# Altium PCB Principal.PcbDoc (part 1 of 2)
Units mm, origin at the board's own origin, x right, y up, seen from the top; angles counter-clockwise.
Board outline 45.4 x 70.2 mm, 2 copper layers (Top Layer, Bottom Layer); 50 components, 70 nets, 241 pads, 58 vias.
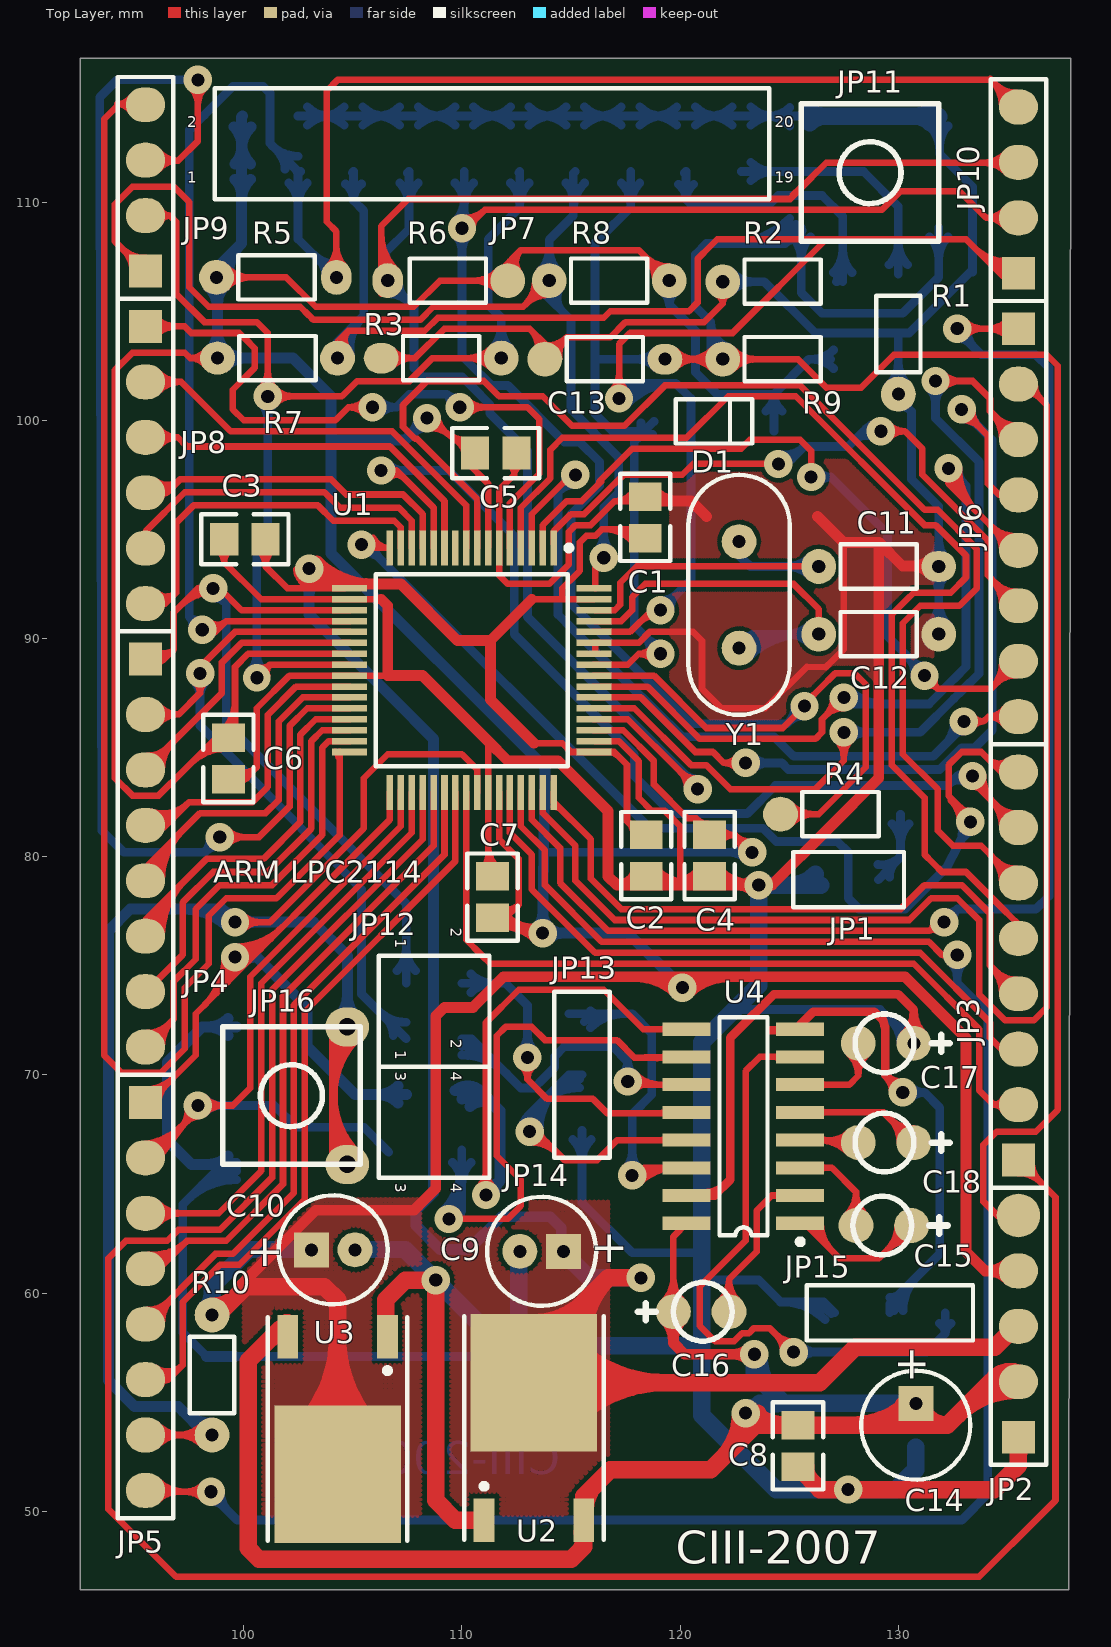
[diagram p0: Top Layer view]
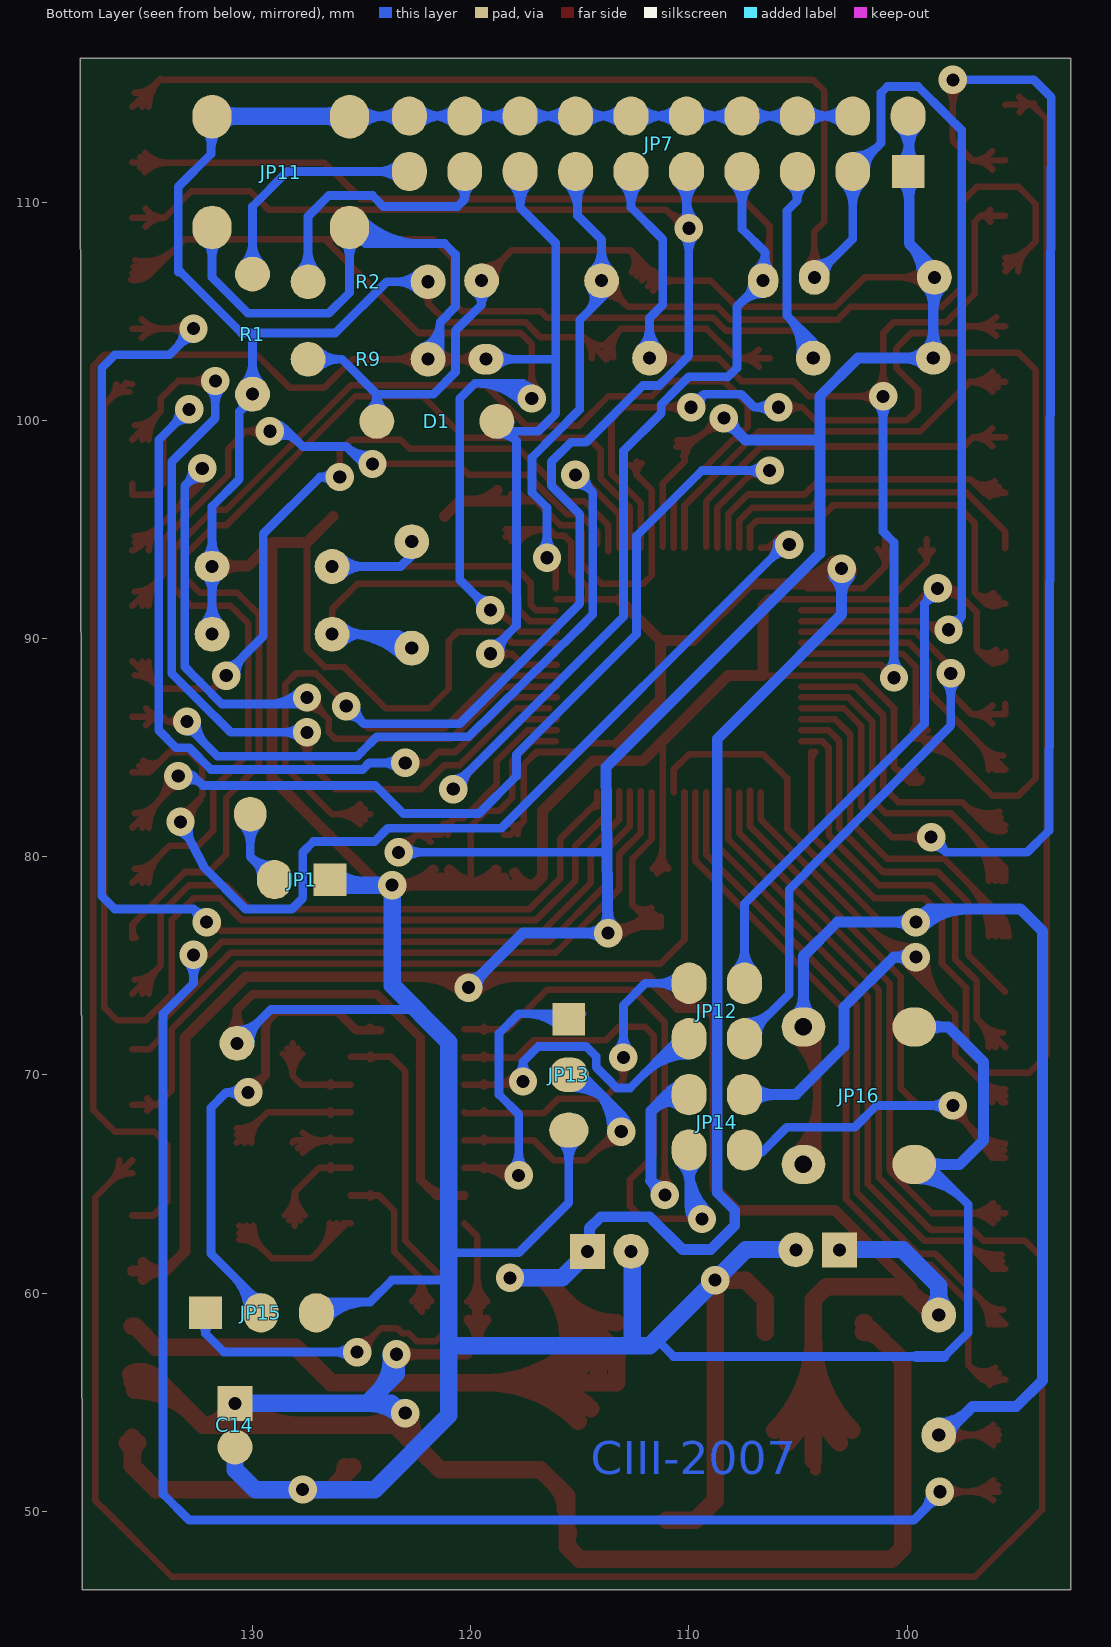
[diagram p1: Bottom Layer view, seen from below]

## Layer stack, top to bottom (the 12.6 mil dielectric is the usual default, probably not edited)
Top Layer: signal copper 0.0356
Dielectric: core 0.32, FR-4, Dk 4.8
Bottom Layer: signal copper 0.0356

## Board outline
92.5,116.4 92.5,46.4 137.8,46.4 137.9,116.6 92.5,116.6

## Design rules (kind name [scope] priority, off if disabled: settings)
Clearance [All] p1: gap=0.2
ComponentClearance [All] p1: gap=0.254 collisioncheckmode=0
PolygonConnect [All] p1: connectstyle=Direct reliefconductorwidth=0.254 reliefentries=4 polygonreliefangle="90 Angle"
RoomDefinition Principal1 [InComponentClass('Principal1')] p1: confinementstyle=ConfineIn formatcopy=TRUE outline 0,0 50.8,0 50.8,25.4 0,25.4
RoutingLayers [All] p1: top layer="Not Used" bottom layer="Not Used"
RoutingVias [All] p1: holewidth=0.711 width=1.27 viastyle="Through Hole" minholewidth=0.711 minwidth=1.27 maxholewidth=0.711 maxwidth=1.27
SolderMaskExpansion [All] p1: expansion=0.102
TestPointUsage [All] p1: valid=0 allowmultiple=FALSE
Testpoint [All] p1: side=15 testpointundercomponent=TRUE minsize=1.016 maxsize=2.54 preferedsize=1.524 minholesize=0 maxholesize=1.016 preferedholesize=0.813 testpointgrid=0.025 style=1023 order=-539222988
Width [All] p1: maxlimit=0.8 minlimit=0.2 preferedwidth=0.2 toplayer_prefwidth=0.3 bottomlayer_prefwidth=0.4 minimp=50.000000 maximp=50.000000 favimp=50.000000
16 further rules are at their usual default settings.

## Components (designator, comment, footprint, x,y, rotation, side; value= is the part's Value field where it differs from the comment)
C1 "Cap" R2012-0805 118.4,95.55 r270 top
C2 "Cap" R2012-0805 118.45,80.05 r90 top
C3 "Cap" R2012-0805 100.05,94.55 r0 top
C4 "Cap" R2012-0805 121.35,80.05 r90 top
C5 "Cap" R2012-0805 111.55,98.5 r180 top
C6 "Cap" R2012-0805 99.3,84.5 r90 top
C7 "Cap" R2012-0805 111.4,78.15 r270 top
C8 "Cap" R2012-0805 125.4,53 r90 top
C9 "Cap" CAPPR2-5x6.8#1 113.652,61.916 r180 top
C10 "Cap" CAPPR2-5x6.8#1 104.098,61.984 r0 top
C11 "Cap" "Res 5mm"#1 126.35,93.3 r0 top
C12 "Cap" "Res 5mm"#2 126.35,90.2 r0 top
C13 "Cap" "Res 5mm"#3 119.3,102.8 r180 top
C14 "Cap Pol1" CAPPR2-5x6.8#2 130.8,53.95 r270 top
C15 "Cap Pol3" CAP_ELECT1#1 130.6,63.1 r180 top
C16 "Cap Pol3" CAP_ELECT1#1 119.7,59.15 r0 top
C17 "Cap Pol3" CAP_ELECT1#2 130.7,71.45 r180 top
C18 "Cap" CAP_ELECT1#1 130.7,66.9 r180 top
D1 "Diode" "Diode 5mm" 118.8,99.95 r0 top
JP1 "JTAG" HDR1X2 126.45,78.95 r0 top
JP2 "Header 5" HDR1X5 135.5,53.4 r90 top
JP3 "Header 8" HDR1X8 135.5,66.1 r90 top
JP4 "Header 8" HDR1X8 95.5,89.06 r270 top
JP5 "Header 8" HDR1X8 95.5,68.74 r270 top
JP6 "Header 8" HDR1X8 135.5,104.2 r270 top
JP7 "JTAG P5" HDR2X10 99.95,111.4 r0 top
JP8 "Header 6" HDR1X6 95.5,104.3 r270 top
JP9 "Header 4" HDR1X4 95.5,106.84 r90 top
JP10 "Header 4" HDR1X4 135.5,106.74 r90 top
JP11 "Header 2" SW1#1 131.85,108.2 r90 top
JP12 "Header 2X2" HDR2X2 107.45,74.2 r270 top
JP13 "Header 3" HDR1X3 115.5,72.55 r270 top
JP14 "Header 2X2" HDR2X2 107.45,69.1 r270 top
JP15 "Header 3" HDR1X3 132.15,59.1 r180 top
JP16 "Header 2" SW1#2 99.035,65.9 r0 top
R1 "Res1" "Res 5mm"#4 130,106.7 r270 top
R2 "Res1" "Res 5mm"#4 127.45,106.35 r180 top
R3 "Res1" "Res 5mm"#5 111.8,102.85 r180 top
R4 "Res1" "Res 5mm"#6 124.6,81.95 r0 top
R5 "Res1" "Res 5mm"#7 98.75,106.55 r0 top
R6 "Res1" "Res 5mm"#8 112.1,106.4 r180 top
R7 "Res1" "Res 5mm"#9 98.8,102.85 r0 top
R8 "Res1" "Res 5mm"#2 119.5,106.4 r180 top
R9 "Res1" "Res 5mm"#10 121.95,102.8 r0 top
R10 "Res1" "Res 5mm"#2 98.55,59 r270 top
U1 "LPC2114/LPC2124" F-QFP10X10-G64/P.5N 110.45,88.55 r270 top
U2 "LD1117S18" KTP02 113.3,52.75 r0 top
U3 "LD1117S33" KTP02 104.3,54.85 r180 top
U4 "MAX232EWE" SO-G16 122.9,67.65 r90 top
Y1 "XTAL 16Mhz" Cristal 122.7,92 r90 top

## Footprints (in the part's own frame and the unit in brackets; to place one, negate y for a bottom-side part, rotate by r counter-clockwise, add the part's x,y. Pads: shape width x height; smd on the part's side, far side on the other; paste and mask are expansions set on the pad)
CAP_ELECT1#1 [mm]
  round 1.6 smd: 1(-0.01,0) 2(2.54,0)
  silkscreen extent -1.65,-1.34 2.68,1.34
CAP_ELECT1#2 [mm]
  round 1.6 hole 0.6: 1(-0.01,0)
  round 1.6 smd: 2(2.54,0)
  silkscreen extent -1.65,-1.34 2.68,1.34
CAPPR2-5x6.8#1 [mm] "Capacitor, Electrolytic, Radial; Body 5 x 6.8 mm (Dia.xH typ); Pin Spacing 2 mm (typ)"
  rect 1.6x1.6 hole 0.6: 1(-1,0)
  round 1.6 hole 0.6: 2(1,0)
  silkscreen extent -2.5,-2.5 2.5,2.5
CAPPR2-5x6.8#2 [mm] "Capacitor, Electrolytic, Radial; Body 5 x 6.8 mm (Dia.xH typ); Pin Spacing 2 mm (typ)"
  rect 1.6x1.6 hole 0.6: 1(-1,0)
  round 1.6 smd far side: 2(1,0)
  silkscreen extent -2.5,-2.5 2.5,2.5
Cristal [mm]
  round 1.6 hole 0.6: 1(-2.44,0) 2(2.44,0)
  silkscreen extent -5.5,-2.32 5.5,2.32
"Diode 5mm" [mm]
  round 1.6 smd far side: 1(0,0) 2(5.5,0)
  silkscreen extent 1,-1.02 4.5,1.02
F-QFP10X10-G64/P.5N [mm]
  rect 1.6x0.3 smd: 1(-5.6,3.75) 2(-5.6,3.25) 3(-5.6,2.75) 4(-5.6,2.25) 5(-5.6,1.75) 6(-5.6,1.25) 7(-5.6,0.75) 8(-5.6,0.25) 9(-5.6,-0.25) 10(-5.6,-0.75) 11(-5.6,-1.25) 12(-5.6,-1.75) 13(-5.6,-2.25) 14(-5.6,-2.75) 15(-5.6,-3.25) 16(-5.6,-3.75) 33(5.6,-3.75) 34(5.6,-3.25) 35(5.6,-2.75) 36(5.6,-2.25) 37(5.6,-1.75) 38(5.6,-1.25) 39(5.6,-0.75) 40(5.6,-0.25) 41(5.6,0.25) 42(5.6,0.75) 43(5.6,1.25) 44(5.6,1.75) 45(5.6,2.25) 46(5.6,2.75) 47(5.6,3.25) 48(5.6,3.75)
  rect 0.3x1.6 smd: 17(-3.75,-5.6) 18(-3.25,-5.6) 19(-2.75,-5.6) 20(-2.25,-5.6) 21(-1.75,-5.6) 22(-1.25,-5.6) 23(-0.75,-5.6) 24(-0.25,-5.6) 25(0.25,-5.6) 26(0.75,-5.6) 27(1.25,-5.6) 28(1.75,-5.6) 29(2.25,-5.6) 30(2.75,-5.6) 31(3.25,-5.6) 32(3.75,-5.6) 49(3.75,5.6) 50(3.25,5.6) 51(2.75,5.6) 52(2.25,5.6) 53(1.75,5.6) 54(1.25,5.6) 55(0.75,5.6) 56(0.25,5.6) 57(-0.25,5.6) 58(-0.75,5.6) 59(-1.25,5.6) 60(-1.75,5.6) 61(-2.25,5.6) 62(-2.75,5.6) 63(-3.25,5.6) 64(-3.75,5.6)
  silkscreen extent -5.72,-4.4 4.4,4.58
HDR1X2 [mm]
  rect 1.5x1.5 smd far side: 1(0,0)
  oval 1.6x1.8 smd far side: 2(2.54,0)
  silkscreen extent -1.27,-1.27 3.81,1.27
HDR1X3 [mm]
  rect 1.5x1.5 smd far side: 1(0,0)
  oval 1.6x1.8 smd far side: 2(2.54,0) 3(5.08,0)
  silkscreen extent -1.27,-1.27 6.35,1.27
HDR1X4 [mm]
  rect 1.5x1.5 smd: 1(0,0)
  oval 1.6x1.8 smd: 2(2.54,0) 3(5.08,0) 4(7.62,0)
  silkscreen extent -1.27,-1.27 8.89,1.27
HDR1X5 [mm]
  rect 1.5x1.5 smd: 1(0,0)
  oval 1.6x1.8 smd: 2(2.54,0) 3(5.08,0) 4(7.62,0)
  round 2 smd: 5(10.16,0)
  silkscreen extent -1.27,-1.27 11.43,1.27
HDR1X6 [mm]
  rect 1.5x1.5 smd: 1(0,0)
  oval 1.6x1.8 smd: 2(2.54,0) 3(5.08,0) 4(7.62,0) 5(10.16,0) 6(12.7,0)
  silkscreen extent -1.27,-1.27 13.97,1.27
HDR1X8 [mm]
  rect 1.5x1.5 smd: 1(0,0)
  oval 1.6x1.8 smd: 2(2.54,0) 3(5.08,0) 4(7.62,0) 5(10.16,0) 6(12.7,0) 7(15.24,0) 8(17.78,0)
  silkscreen extent -1.27,-1.27 19.05,1.27
HDR2X2 [mm]
  oval 1.9x1.6 smd far side: 1(0,0) 2(0,2.54) 3(2.54,0) 4(2.54,2.54)
  silkscreen extent -1.27,-1.27 3.81,3.81
HDR2X10 [mm]
  rect 1.5x1.5 smd far side: 1(0,0)
  oval 1.6x1.8 smd far side: 2(0,2.54) 3(2.54,0) 4(2.54,2.54) 5(5.08,0) 6(5.08,2.54) 7(7.62,0) 8(7.62,2.54) 9(10.16,0) 10(10.16,2.54) 11(12.7,0) 12(12.7,2.54) 13(15.24,0) 14(15.24,2.54) 15(17.78,0) 16(17.78,2.54) 17(20.32,0) 18(20.32,2.54) 19(22.86,0) 20(22.86,2.54)
  silkscreen extent -1.27,-1.27 24.13,3.81
KTP02 [mm] "PowerFLEX (D-PAK/TO-252-AA); 3 Leads (1 Cropped); Body 9.7 (inc. leads) x 6.2 mm (LxW max)"
  rect 0.95x2 smd: 1(-2.285,-3.15) 3(2.285,-3.15)
  rect 5.8x6.3 smd: 4(0,3.15)
  silkscreen extent -3.2,-4.05 3.2,6.2
R2012-0805 [mm]
  rect 1.3x1.5 smd: 1(-0.95,0) 2(0.95,0)
  silkscreen extent -2,-1.15 2,1.15
"Res 5mm"#1 [mm]
  round 1.6 hole 0.6: 1(0,0)
  oval 1.6x1.4 hole 0.6: 2(5.5,0)
  silkscreen extent 1,-1.02 4.5,1.02
"Res 5mm"#2 [mm]
  round 1.6 hole 0.6: 1(0,0) 2(5.5,0)
  silkscreen extent 1,-1.02 4.5,1.02
"Res 5mm"#3 [mm]
  oval 1.6x1.4 hole 0.6: 1(0,0)
  round 1.6 smd: 2(5.5,0)
  silkscreen extent 1,-1.02 4.5,1.02
"Res 5mm"#4 [mm]
  round 1.6 smd far side: 1(0,0)
  round 1.6 hole 0.6: 2(5.5,0)
  silkscreen extent 1,-1.02 4.5,1.02
"Res 5mm"#5 [mm]
  round 1.6 hole 0.6: 1(0,0)
  oval 1.6x1.4 smd: 2(5.5,0)
  silkscreen extent 1,-1.02 4.5,1.02
"Res 5mm"#6 [mm]
  round 1.6 smd: 1(0,0)
  oval 1.5x1.6 smd far side: 2(5.5,0)
  silkscreen extent 1,-1.02 4.5,1.02
"Res 5mm"#7 [mm]
  round 1.6 hole 0.6: 1(0,0)
  oval 1.4x1.6 hole 0.6: 2(5.5,0)
  silkscreen extent 1,-1.02 4.5,1.02
"Res 5mm"#8 [mm]
  round 1.6 smd: 1(0,0)
  oval 1.4x1.6 hole 0.6: 2(5.5,0)
  silkscreen extent 1,-1.02 4.5,1.02
"Res 5mm"#9 [mm]
  oval 1.6x1.5 hole 0.6: 1(0,0)
  round 1.6 hole 0.6: 2(5.5,0)
  silkscreen extent 1,-1.02 4.5,1.02
"Res 5mm"#10 [mm]
  round 1.6 hole 0.6: 1(0,0)
  round 1.6 smd far side: 2(5.5,0)
  silkscreen extent 1,-1.02 4.5,1.02
SO-G16 [mm]
  rect 0.6x2.2 smd: 1(-4.445,-2.6) 2(-3.175,-2.6) 3(-1.905,-2.6) 4(-0.635,-2.6) 5(0.635,-2.6) 6(1.905,-2.6) 7(3.175,-2.6) 8(4.445,-2.6) 9(4.445,2.6) 10(3.175,2.6) 11(1.905,2.6) 12(0.635,2.6) 13(-0.635,2.6) 14(-1.905,2.6) 15(-3.175,2.6) 16(-4.445,2.6)
  silkscreen extent -5.42,-2.72 5,1.1
SW1#1 [mm]
  oval 2x1.8 smd far side: 1(0.635,6.3) 1(0.635,0) 2(5.715,6.3) 2(5.715,0)
  silkscreen extent 0,0 6.3,6.3
SW1#2 [mm]
  oval 2x1.8 smd far side: 1(0.635,0) 1(0.635,6.3)
  oval 2x1.8 hole 0.8: 2(5.715,0) 2(5.715,6.3)
  silkscreen extent 0,0 6.3,6.3

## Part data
C1 C2 C3 C4 C5 C6 C7 C8 C9 C10 C11 C12 C13: "Capacitor"
C14: "Polarized Capacitor (Radial)"
C15 C16 C17: "Polarized Capacitor (Surface Mount)"
C18: library part "Cap Pol3", "Polarized Capacitor (Surface Mount)"
D1: "Default Diode"
JP1 JP2: library part "Header 2", "Header, 2-Pin"
JP3 JP4 JP5 JP6: "Header, 8-Pin"
JP7: library part "Header 10X2", "Header, 10-Pin, Dual row"
JP8: "Header, 6-Pin"
JP9: library part "Header 8", "Header, 8-Pin"
JP10: "Header, 4-Pin"
JP11 JP16: "Header, 2-Pin"
JP12 JP14: "Header, 2-Pin, Dual row"
JP13 JP15: "Header, 3-Pin"
R1 R2 R3 R4 R5 R6 R7 R8 R9 R10: "Resistor"
U2 U3: library part LF27ACDT, "Very Low Drop Voltage Regulator with Inhibit"
U4: "+5V Powered RS-232 Driver/Receiver"
Y1: library part XTAL, "Crystal Oscillator"

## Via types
v1: diameter 1.3, hole 0.6, Top Layer to Bottom Layer, 57 vias
v2: diameter 1.27, hole 0.6, Top Layer to Bottom Layer, 1 vias

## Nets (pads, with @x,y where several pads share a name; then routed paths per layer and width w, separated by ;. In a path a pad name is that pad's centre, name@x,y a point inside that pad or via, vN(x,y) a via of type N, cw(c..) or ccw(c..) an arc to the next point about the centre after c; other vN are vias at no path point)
GND: C1.1 C2.1 C3.1 C4.1 C5.1 C6.1 C7.1 C8.1 C9.2 C10.2 C11.2 C12.2 C13.2 C14.2 C17.1 JP1.1 JP2.1 JP7.4 JP7.6 JP7.8 JP7.10 JP7.12 JP7.14 JP7.16 JP7.18 JP7.20 JP11.2 JP13.3 JP15.3 JP16.1 R1.2 R2.2 R3.2 U1.6 U1.18 U1.25 U1.42 U1.50 U1.58 U1.59 U2.1 U3.1 U4.15 | length 502.5
  Top Layer w0.3: C3.1@98.817,94.038 cw(c98.448,93.5) 99.1,93.5 ; C3.1@99.1,94.55 99.1,93.5 ; C6.1@99.3,83.55 100.1,83.6 100.6,84.1 ; C6.1@99.349,83.464 ccw(c99.644,83.962) 100.053,83.553 ; C3.1@99.383,94.038 ccw(c99.752,93.5) 99.1,93.5 ; C6.1@99.502,83.722 ccw(c99.847,84.306) 100.326,83.826 ; C6.1@99.654,83.98 ccw(c100.05,84.65) 100.6,84.1 ; C6.1@99.846,83.777 ccw(c100.13,83.921) 100.15,83.603 ccw(c100.169,83.293) C6.1@99.874,83.391 ; 106.3,91.8 U1.18@104.85,91.8 101.9,91.8 100.8,91.8 99.1,93.5 ; R3.2@106.3,102.85 107.85,102.85 109.2,104.2 113.1,104.2 113.8,103.5 C13.2@113.8,102.8 114.8,103.8 ; 106.6,88.3 105.9,88.3 U1.25@104.85,88.3 102.1,88.3 100.6,86.8 100.6,84.1 ; R3.2@106.789,102.461 cw(c107.728,101.522) 107.728,102.85 cw(c107.728,104.178) R3.2@106.789,103.239 ; C7.1@110.946,79.454 ccw(c110.334,80.066) 111.2,80.066 ; C7.1@111.2,79.4 111.2,85.3 ; 111.2,79.824 ccw(c112.024,79.824) C7.1@111.441,79.241 ; 111.2,80.549 ccw(c112.749,80.549) C7.1@111.654,79.454 ; C5.1@112.163,98.03 cw(c111.675,97.495) 112.4,97.495 cw(c112.883,97.495) C5.1@112.695,97.94 ; C5.1@112.4,98.1 112.4,97.5 111.7,96.8 U1.6@111.7,94.15 111.7,92.9 112.1,92.5 114,92.5 114.9,93.4 114.9,94.893 115.207,95.2 115.9,95.2 116.5,95.8 117,96.3 ; 113.117,104.183 cw(c112.172,103.239) C13.2@113.462,102.891 ; 113.484,103.816 cw(c112.75,103.083) C13.2@113.752,102.813 ; C13.2@113.85,103.448 ccw(c113.942,104.658) 114.8,103.8 ; C13.2@114.448,102.85 cw(c115.658,102.942) 114.8,103.8 ; U1.59@116.05,89.8 118.1,89.8 118.6,90.3 120.6,90.3 121,89.9 121,87.7 121.9,86.8 123.9,86.8 125.8,88.7 126.682,88.69 126.972,88.979 126.99,88.99 127.5,89.5 127.5,94.4 ; U1.50@116.1,85.3 117.186,85.3 118.1,84.386 118.1,82.7 118.7,82.1 119.3,82.1 120,81.4 120,78.7 ; U1.58@116.1,89.3 U1.59@116.1,89.8 ; 117.557,96.3 ccw(c117.557,96.99) C1.1@118.133,96.61 ; 117.576,96.3 cw(c117.576,95.776) C1.1@117.946,96.146 ; C1.1@117.883,96.775 cw(c117,97.357) 117,96.3 ; C1.1@118.2,96.3 117,96.3 ; R2.2@121.686,105.756 cw(c121.506,105.35) 121.95,105.35 ; R2.2@121.95,106.35 121.95,105.35 ; R2.2@122.214,105.756 ccw(c122.394,105.35) 121.95,105.35 ; 114.8,103.8 116.8,103.8 117.5,104.5 121.1,104.5 121.95,105.35
  Top Layer w0.4: U4.15@120.3,64.475 121.575,64.475 122.3,65.2 122.3,71.7 122.596,71.996 124.3,73.7 130,73.7 130.71,72.99 C17.1@130.71,71.45 ; U4.15@121.1,64.575 ccw(c121.1,65.963) 122.082,64.982 ; C17.1@130.286,71.874 ccw(c129.261,72.898) 130.71,72.898 ccw(c132.159,72.898) C17.1@131.134,71.874
  Top Layer w0.5: 106.3,91.8 106.6,91.5 106.6,88.3 108.2,88.3 111.2,85.3 112.1,84.4 114.4,84.4 116.7,82.1 116.7,79.1 117.1,78.7 ; C2.1@117.987,79.268 cw(c117.1,79.677) 117.1,78.7 ; C1.1@118.2,96.3 120.5,96.3 121.2,95.6 ; C2.1@118.479,79.029 ccw(c119.274,79.824) 119.274,78.7 ; C1.1@118.783,96.783 ccw(c119.949,97.949) 119.949,96.3 ; C2.1@118.833,79.383 ccw(c120.481,81.031) 120.481,78.7 ; 119.319,78.7 ccw(c119.319,81.031) C4.1@120.967,79.383 ; 120.526,78.7 ccw(c120.526,79.824) C4.1@121.321,79.029 ; C4.1@121.379,79.029 ccw(c122.174,79.824) 122.174,78.7 ; C4.1@121.733,79.383 ccw(c123.381,81.031) v1@123.381,78.7 ; v1@123.328,78.428 ccw(c122.671,77.771) 122.671,78.7 ccw(c122.671,79.629) v1@123.328,78.972 ; 126.3,95.6 127.5,94.4 129.114,94.4 ; 126.45,80.95 126.8,81.3 ; 130.63,93.314 cw(c130.63,92.18) C11.2@131.432,92.982 ; 130.698,93.314 ccw(c130.698,94.352) C11.2@131.432,93.618 ; C11.2@131.5,93.314 130.2,93.314 129.114,94.4 ; 117.1,78.7 124.2,78.7 126.8,81.3 ; 126.8,81.3 129.1,83.6 129.1,94.386 129.114,94.4
  Top Layer w0.8: U3.1@106.5,58.2 106.5,59.7 107.4,60.6 v1(108.8,60.6) 108.8,50.5 109.7,49.6 U2.1@111.015,49.6 ; C8.1@125.4,52.05 126.4,51 134.4,51 135.5,52.1 JP2.1@135.5,53.4 ; C8.1@125.75,52.044 ccw(c126.6,52.023) C8.1@125.984,51.436 ; JP2.1@135.253,53.153 cw(c134.655,52.555) 135.5,52.555 cw(c136.345,52.555) JP2.1@135.747,53.153
  Bottom Layer w0.4: 97.391,64.256 cw(c99.67,61.977) JP16.1@99.67,65.2 ; 98.074,64.939 cw(c99.67,63.343) JP16.1@99.67,65.6 ; 98.3,57.1 97.2,58.2 97.2,64.065 JP16.1@99.035,65.9 ; JP16.1@98.757,65.622 cw(c99.67,64.708) JP16.1@99.67,66 ; 99.6,57.1 110.7,57.1 111.5,57.9 ; JP7.4@102.49,113.94 129.5,113.94 ; JP7.4@102.914,113.516 cw(c103.939,112.491) 103.939,113.94 cw(c103.939,115.389) JP7.4@102.914,114.364 ; JP7.6@104.606,113.516 ccw(c103.581,112.491) 103.581,113.94 ccw(c103.581,115.389) JP7.6@104.606,114.364 ; JP7.6@105.454,113.516 cw(c106.479,112.491) 106.479,113.94 cw(c106.479,115.389) JP7.6@105.454,114.364 ; JP7.8@107.146,113.516 ccw(c106.121,112.491) 106.121,113.94 ccw(c106.121,115.389) JP7.8@107.146,114.364 ; JP7.8@107.994,113.516 cw(c109.019,112.491) 109.019,113.94 cw(c109.019,115.389) JP7.8@107.994,114.364 ; JP7.10@109.686,113.516 ccw(c108.661,112.491) 108.661,113.94 ccw(c108.661,115.389) JP7.10@109.686,114.364 ; JP7.10@110.534,113.516 cw(c111.559,112.491) 111.559,113.94 cw(c111.559,115.389) JP7.10@110.534,114.364 ; JP7.12@112.226,113.516 ccw(c111.201,112.491) 111.201,113.94 ccw(c111.201,115.389) JP7.12@112.226,114.364 ; JP7.12@113.074,113.516 cw(c114.099,112.491) 114.099,113.94 cw(c114.099,115.389) JP7.12@113.074,114.364 ; JP7.14@114.766,113.516 ccw(c113.741,112.491) 113.741,113.94 ccw(c113.741,115.389) JP7.14@114.766,114.364 ; JP13.3@115.076,67.046 cw(c114.051,66.021) 115.5,66.021 cw(c116.949,66.021) JP13.3@115.924,67.046 ; JP13.3@115.5,67.47 115.5,64.149 117.8,61.849 121,61.849 ; JP7.14@115.614,113.516 cw(c116.639,112.491) 116.639,113.94 cw(c116.639,115.389) JP7.14@115.614,114.364 ; JP7.16@117.306,113.516 ccw(c116.281,112.491) 116.281,113.94 ccw(c116.281,115.389) JP7.16@117.306,114.364 ; JP7.16@118.154,113.516 cw(c119.179,112.491) 119.179,113.94 cw(c119.179,115.389) JP7.16@118.154,114.364 ; JP7.18@119.846,113.516 ccw(c118.821,112.491) 118.821,113.94 ccw(c118.821,115.389) JP7.18@119.846,114.364 ; JP7.18@120.694,113.516 cw(c121.719,112.491) 121.719,113.94 cw(c121.719,115.389) JP7.18@120.694,114.364 ; 121,60.6 123.6,60.6 124.6,59.6 126.57,59.6 JP15.3@127.07,59.1 ; R2.2@121.95,106.35 123.85,106.35 126.2,104 130.5,104 133.3,106.8 133.4,106.8 133.4,110.7 131.9,112.2 JP11.2@131.9,113.915 ; R2.2@122.374,105.926 cw(c123.399,104.901) 123.399,106.35 cw(c123.399,107.799) R2.2@122.374,106.774 ; JP7.20@122.386,113.516 ccw(c121.361,112.491) 121.361,113.94 ccw(c121.361,115.389) JP7.20@122.386,114.364 ; 122.6,73.1 122.7,73 129.16,73 C17.1@130.71,71.45 ; JP7.20@123.234,113.516 cw(c124.259,112.491) 124.259,113.94 cw(c124.259,115.389) JP7.20@123.234,114.364 ; 123.941,113.94 cw(c123.941,112.406) JP11.2@125.026,113.491 ; 124.062,113.94 ccw(c124.062,115.303) JP11.2@125.026,114.339 ; 124.656,59.6 cw(c124.656,56.786) JP15.3@126.646,58.776 ; 125.621,59.6 cw(c125.621,57.751) JP15.3@126.929,59.059 ; JP11.2@126.074,113.491 cw(c127.159,112.406) 127.159,113.94 ; JP11.2@126.074,114.339 ccw(c127.038,115.303) 127.038,113.94 ; R1.2@129.576,101.624 ccw(c128.551,102.649) 130,102.649 ccw(c131.449,102.649) R1.2@130.424,101.624 ; R1.2@129.9,101.2 R1.2@129.939,101.151 ; R1.2@130,101.075 R1.2@130.3,100.7 ; 130,104 130,101 130.6,100.4 130.6,97.3 131.85,96.05 C12.2@131.85,89.95 ; C17.1@130.11,71.45 ccw(c128.661,71.45) 129.686,72.474 ccw(c130.71,73.498) C17.1@130.71,72.05 ; R1.2@130.122,100.613 cw(c130.207,100.207) 130.5,100.5 cw(c130.681,100.681) R1.2@130.477,100.836 ; C12.2@131.426,90.624 ccw(c130.401,91.649) 131.85,91.649 ccw(c133.299,91.649) C12.2@132.274,90.624 ; JP11.2@131.426,113.491 cw(c130.281,112.346) 131.9,112.346 ; C11.2@131.496,92.946 cw(c130.643,92.093) 131.85,92.093 cw(c133.057,92.093) C11.2@132.204,92.946 ; C11.2@131.496,93.654 ccw(c130.643,94.507) 131.85,94.507 ccw(c133.057,94.507) C11.2@132.204,93.654 ; 131.9,112.587 cw(c133.178,112.587) JP11.2@132.274,113.491
  Bottom Layer w0.5: 98.3,57.1 99.6,57.1 ; JP16.1@99.281,65.511 ccw(c98.342,64.572) 98.342,65.9 ccw(c98.342,67.228) JP16.1@99.281,66.289 ; JP16.1@99.281,71.811 ccw(c98.342,70.872) 98.342,72.2 ccw(c98.342,73.528) JP16.1@99.281,72.589 ; JP16.1@99.67,65.9 97.6,65.9 96.5,67 96.5,70.6 98.1,72.2 JP16.1@99.67,72.2
  Bottom Layer w0.8: C10.2@105.2,62 107.4,62 111.8,57.6 120.9,57.6 121,57.5 ; C9.2@112.391,61.791 cw(c111.886,61.286) C9.2@112.6,61.286 ; 112.5,57.6 112.55,57.65 ; 112.6,57.6 C9.2@112.6,61.9 ; 125.002,78.7 ccw(c125.002,80.398) JP1.1@126.202,79.197 ; JP11.2@125.933,113.632 cw(c126.676,112.889) 126.676,113.94 ; JP11.2@125.933,114.198 ccw(c126.555,114.82) 126.555,113.94 ; JP11.2@126,113.94 131.825,113.94 JP11.2@131.85,113.915 ; JP1.1@126.45,78.7 v1(123.6,78.7) 123.6,74.1 121,71.5 121,54.4 124.4,51 129.882,51 130.527,51.645 130.8,51.918 C14.2@130.8,52.95 ; 130.724,113.94 cw(c130.724,112.889) JP11.2@131.467,113.632 ; 130.845,113.94 ccw(c130.845,114.82) JP11.2@131.467,114.198
  other v1: 127.7,51
NetC1_2: C1.2 C2.2 C3.2 C9.1 JP2.3 U1.17 U1.49 U1.63 U2.4 | length 169.5
  Top Layer w0.3: C3.2@100.659,94.084 cw(c99.928,93.3) 101,93.3 ; C3.2@101,94.55 101,93.3 ; C3.2@101.341,94.084 ccw(c102.072,93.3) 101,93.3 ; v1@102.413,93.167 ccw(c103.33,93.219) 103.33,92.3 ; v1@102.712,93.184 ccw(c103.648,93.237) 103.648,92.3 ; v1@103.012,93.201 ccw(c103.965,93.255) 103.965,92.3 ; v1@103.312,93.218 ccw(c104.283,93.273) U1.17@104.283,92.3 ; v1@103.611,93.235 ccw(c104.6,93.291) 104.6,92.3 102,92.3 101,93.3 ; 113.2,91.8 U1.63@116.05,91.8 ; 113.3,85.2 114.6,85.2 115,84.8 116.979,84.8 117.564,84.215 117.564,81.636 118.2,81 C2.2@118.45,81 ; 114.6,91.8 114.6,92.3 115.202,92.897 115.4,93.1 ; 115.2,92.9 115.4,93.1 ; 116.6,95 cw(c116.6,93.445) C1.2@117.886,94.319 ; U1.49@116.7,84.8 cw(c116.7,84.127) 117.176,84.603 ; 117.167,95 cw(c117.167,93.83) C1.2@118.135,94.488 ; C1.2@117.733,95 cw(c117.733,94.215) C1.2@118.383,94.656 ; C2.2@117.85,81.02 ccw(c117.127,81.049) 117.639,81.561 ccw(c117.972,81.894) C2.2@118.155,81.46 ; C1.2@118.4,95 116.407,95 116.107,94.7 115.7,94.7 115.5,94.5 115.4,94.4 115.4,93.1
  Top Layer w0.5: v1@102.655,92.855 ccw(c103.512,93.712) 103.512,92.5 ; v1(103,93.2) 103.7,92.5 ; v1@103.008,93.208 ccw(c104.719,94.919) 104.719,92.5 ; v1@103.086,92.695 cw(c103.204,92.004) 103.7,92.5 ; v1@103.362,93.562 ccw(c105.926,96.126) 105.926,92.5 ; v1@103.505,93.114 ccw(c104.196,92.996) 103.7,92.5 ; 113.2,91.8 111.3,89.9 ; 113.3,85.2 111.3,87.2 111.3,89.9 ; 103.7,92.5 107.2,92.5 109.8,89.9 111.3,89.9
  Top Layer w0.8: U2.4@113.3,58.65 ccw(c113.3,61.909) 115.605,59.605 ; U2.4@114.165,56.399 cw(c116.493,57.067) U2.4@114.78,58.78 ; U2.4@114.502,54.698 cw(c117.404,51.796) 117.404,55.9 cw(c117.404,60.004) U2.4@114.502,57.102 ; U2.4@114.934,56.619 cw(c117.984,57.496) 115.74,59.74 ; U2.4@115.068,54.132 cw(c119.336,49.864) 119.336,55.9 cw(c119.336,61.936) U2.4@115.068,57.668 ; U2.4@115.703,56.84 cw(c119.475,57.924) 116.7,60.7 ; v1(118.2,60.7) 116.7,60.7 ; JP2.3@135.5,58.48 135.38,58.48 134.423,57.523 128.023,57.523 126.4,55.9 U2.4@113.3,55.9 113.3,57.3 116.7,60.7
  Bottom Layer w0.5: v1@102.638,92.838 cw(c101.764,91.964) 103,91.964 cw(c104.236,91.964) v1@103.362,92.838 ; v1(103,93.2) 103,91.1 106.837,87.263 108.7,85.4 108.7,64.6 107.9,63.8 107.9,63.1 109,62 110.3,62 111.8,63.5 114.032,63.5 114.55,62.982 C9.1@114.55,61.95
  Bottom Layer w0.8: C9.1@114.55,61.95 115.8,60.7 v1(118.2,60.7)
NetC4_2: C4.2 C5.2 C6.2 C7.2 C10.1 D1.2 JP2.4 JP7.1 JP7.2 R5.1 R6.1 R7.1 R8.1 R9.2 R10.1 U1.7 U1.23 U1.43 U1.51 U3.4 | length 344
  Top Layer w0.3: 97.578,84.278 cw(c99.2,82.657) C6.2@99.2,84.95 ; 98.09,84.79 cw(c99.2,83.681) C6.2@99.2,85.25 ; R7.1@98.27,102.49 ccw(c97.55,101.95) 97.55,102.85 ; R7.1@98.27,103.21 cw(c97.55,103.75) 97.55,102.85 ; R7.1@98.6,102.85 97.55,102.85 ; R5.1@98.75,106.55 101.95,106.55 103.3,105.2 107.793,105.2 108.993,106.4 111.8,106.4 111.8,106.9 112.7,107.8 ; R5.1@98.997,106.303 cw(c99.595,105.705) 99.595,106.55 cw(c99.595,107.395) R5.1@98.997,106.797 ; C6.2@99.046,85.804 ccw(c97.71,87.14) 99.6,87.14 ; R5.1@99.21,106.09 cw(c100.319,104.981) 100.319,106.55 cw(c100.319,108.119) R5.1@99.21,107.01 ; C6.2@99.259,85.591 ccw(c98.434,86.416) 99.6,86.416 ; 99.6,86.174 ccw(c100.124,86.174) C6.2@99.754,85.804 ; U1.23@104.85,89.3 100.2,89.3 99.6,88.7 99.6,85.4 98.7,85.4 97.3,84 96.1,82.8 94.9,82.8 94.1,83.6 94.1,102.3 94.9,103.1 97.3,103.1 97.55,102.85 ; v1(108.4,100.1) 110.1,98.8 C5.2@110.25,98.35 ; v1@108.464,99.619 cw(c108.619,98.459) 109.33,99.389 cw(c110.041,100.319) v1@108.881,100.164 ; 109.275,99.431 ccw(c110.309,100.782) C5.2@110.534,99.096 ; 109.831,99.006 cw(c109.398,98.44) C5.2@110.104,98.534 ; 109.851,98.991 ccw(c110.444,99.767) C5.2@110.574,98.798 ; C5.2@110.2,98.65 110.2,98.1 111.2,97.1 U1.7@111.2,94.2 ; C7.2@111.417,77.144 ccw(c112.067,77.585) C7.2@112.067,76.8 ; C7.2@111.587,77.38 ccw(c111.859,77.944) 112.301,77.501 ; R6.1@111.64,105.94 ccw(c110.531,104.831) 110.531,106.4 ccw(c110.531,107.969) R6.1@111.64,106.86 ; C7.2@111.665,77.312 ccw(c112.633,77.97) 112.633,76.8 ; U1.43@111.7,82.95 111.7,80.8 112.6,79.9 112.6,77.8 ; C7.2@111.717,77.65 ccw(c112.053,78.347) 112.6,77.8 ; C7.2@111.805,76.8 cw(c111.805,74.605) v1@113.357,76.157 ; R6.1@111.853,106.153 ccw(c111.255,105.555) 111.255,106.4 ccw(c111.255,107.245) R6.1@111.853,106.647 ; C7.2@111.914,77.481 ccw(c113.2,78.355) v1@113.2,76.8 ; R6.1@112.14,106.43 cw(c112.683,106.83) 112.206,107.306 ; R6.1@112.382,106.608 cw(c112.968,107.039) 112.453,107.553 ; 112.529,76.8 cw(c112.529,75.329) v1@113.569,76.369 ; R6.1@112.623,106.785 cw(c113.252,107.248) 112.7,107.8 ; v1(113.7,76.5) v1@113.2,76.8 ; U1.51@116.05,85.8 117.393,85.8 118.8,84.393 118.8,83.307 120.339,81.768 120.732,81.768 ; R8.1@118.85,106.4 ccw(c117.281,106.4) 118.39,107.51 ccw(c119.5,108.619) R8.1@119.5,107.05 ; R8.1@119.15,106.4 ccw(c118.305,106.4) 118.903,106.997 ccw(c119.5,107.595) R8.1@119.5,106.75 ; R8.1@119.5,106.4 118.1,107.8 112.7,107.8 ; 120.823,81.677 ccw(c121.25,82.104) C4.2@121.25,81.5 ; C4.2@121.05,81 ccw(c119.964,81) 120.732,81.768 ; C4.2@121.2,81.3 120.732,81.768 ; C4.2@121.35,81 122.5,81 ; C4.2@121.4,81.1 121.425,81.075 C4.2@121.5,81 ; C4.2@121.838,80.685 cw(c122.5,80.148) 122.5,81 ; C4.2@121.838,81.315 ccw(c122.5,81.852) 122.5,81 ; v1@122.815,80.212 ccw(c121.739,80.238) 122.5,81 ccw(c123.262,81.761) v1@123.288,80.685 ; v1(123.3,80.2) 122.5,81 ; 112.6,77.8 112.05,77.25 111.3,77.25 111.3,76.8 v1@113.2,76.8
  Top Layer w0.5: 99.8,60.3 103.3,63.8 107.8,63.8 108.8,64.8 108.8,72.7 109.2,73.1 110.5,73.1 111.9,74.5 130.3,74.5 133.1,71.7 133.1,61.9 133.98,61.02 JP2.4@135.5,61.02 ; U3.4@104.204,51.9 U3.4@104.204,52.35 ; 117.963,74.5 cw(c117.963,71.863) v1@119.828,73.728 ; 119.171,74.5 cw(c119.171,73.071) v1@120.181,74.081 ; v1@120.019,74.081 cw(c121.029,73.071) 121.029,74.5 ; v1@120.372,73.728 cw(c122.237,71.863) 122.237,74.5 ; JP2.4@135.011,60.631 ccw(c134.072,59.692) 134.072,61.02 ccw(c134.072,62.348) JP2.4@135.011,61.409
  Top Layer w0.8: R10.1@98.55,59 98.8,59 100.1,60.3 103.7,60.3 104.3,59.7 U3.4@104.3,52.35 ; R10.1@98.55,59.4 ccw(c98.55,60.969) 99.66,59.86 ; U3.4@102.532,53.718 ccw(c98.264,57.986) 104.3,57.986 ccw(c110.336,57.986) U3.4@106.068,53.718 ; U3.4@103.098,53.152 ccw(c100.196,56.054) 104.3,56.054 ccw(c108.404,56.054) U3.4@105.502,53.152
  Bottom Layer w0.4: 113.7,80.2 v1(123.3,80.2) ; R8.1@119.175,105.896 cw(c118.792,105.3) 119.5,105.3 ; R8.1@119.5,106.4 119.5,105.3 ; R8.1@119.825,105.896 ccw(c120.208,105.3) 119.5,105.3 ; v1@122.992,79.892 ccw(c122.25,79.15) 122.25,80.2 ccw(c122.25,81.25) v1@122.992,80.508 ; D1.2@123.925,100.418 ccw(c123.298,101.2) 124.3,101.2 ; D1.2@124.3,99.5 124.3,101.2 ; D1.2@124.675,100.418 cw(c125.302,101.2) 124.3,101.2 ; R9.2@126.9,102.8 125.9,102.8 124.3,101.2 ; R9.2@127.026,102.376 ccw(c126.001,101.351) 126.001,102.8 ccw(c126.001,104.249) R9.2@127.026,103.224 ; 119.5,105.3 120.7,104.1 120.7,102.2 121.7,101.2 124.3,101.2
  Bottom Layer w0.5: R5.1@98.361,106.161 cw(c97.301,105.101) 98.8,105.101 ; R7.1@98.446,103.204 ccw(c97.593,104.057) 98.8,104.057 ccw(c100.007,104.057) R7.1@99.154,103.204 ; 98.8,105.343 cw(c99.957,105.343) R5.1@99.139,106.161 ; R5.1@98.8,106.552 cw(c99.79,106.589) 99.089,107.289 ; R7.1@99.204,102.496 cw(c100.057,101.643) 100.057,102.85 cw(c100.057,104.057) R7.1@99.204,103.204 ; R5.1@99.3,106.571 cw(c101.353,106.647) 99.9,108.1 ; JP7.2@99.561,113.451 cw(c98.743,112.633) 99.9,112.633 ; JP7.1@99.596,111.046 cw(c98.864,110.314) 99.9,110.314 ; JP7.1@99.596,111.754 ccw(c98.864,112.486) 99.9,112.486 ; 99.9,110.072 cw(c101.278,110.072) JP7.1@100.304,111.046 ; 99.9,112.391 cw(c101.399,112.391) JP7.2@100.339,113.451 ; 99.9,112.728 ccw(c101.278,112.728) JP7.1@100.304,111.754 ; JP7.2@99.95,113.94 99.9,113.89 99.9,108.1 ; 104.027,99.1 107.4,99.1 108.3,100 v1(108.4,100.1) ; v1@108.015,100.1 cw(c107.086,100.1) 107.743,99.443 cw(c108.4,98.786) v1@108.4,99.715 ; v1@113.431,76.776 ccw(c112.783,77.442) 113.712,77.429 ccw(c114.642,77.417) v1@113.976,76.769 ; v1@113.5,76.5 117.6,76.5 v1(120.1,74) ; v1(113.7,76.5) 113.749,80.2 113.8,84.1 104,93.9 104,101.1 102.25,102.85 R7.1@98.8,102.85 98.8,107 99.9,108.1 ; v1@113.972,76.228 cw(c114.629,75.571) 114.629,76.5 cw(c114.629,77.429) v1@113.972,76.772 ; v1@119.715,74 ccw(c118.786,74) 119.443,74.657 ccw(c120.1,75.314) v1@120.1,74.385
  Bottom Layer w0.8: R10.1@98.267,59.283 ccw(c97.584,59.966) 98.55,59.966 ccw(c99.516,59.966) R10.1@98.833,59.283 ; R10.1@98.55,59 98.55,60.35 100.2,62 C10.1@103.2,62
NetC8_2: C8.2 C14.1 C16.1 JP2.2 U2.3 U3.3 U4.16 | length 119.1
  Top Layer w0.3: C16.1@119.23,59.61 ccw(c118.121,60.72) 119.69,60.72 ccw(c121.259,60.72) C16.1@120.15,59.61 ; C16.1@119.443,59.398 ccw(c118.845,59.995) 119.69,59.995 ccw(c120.535,59.995) C16.1@119.937,59.398 ; C16.1@119.7,59.14 C16.1@119.69,59.15 119.69,62.595 U4.16@120.3,63.205
  Top Layer w0.5: C16.1@119.301,58.761 cw(c118.362,57.823) 119.69,57.823 cw(c121.018,57.823) C16.1@120.079,58.761 ; C16.1@119.69,59.15 119.69,57.71 120.2,57.2 v1(123.4,57.2) ; v1@123.128,56.928 ccw(c122.471,56.271) 122.471,57.2 ccw(c122.471,58.129) v1@123.128,57.472
  Top Layer w0.8: 101.136,57.836 cw(c102.015,56.957) U3.3@102.015,58.2 ; U3.3@101.657,58.357 100.2,56.9 100.2,48.3 100.7,47.8 115,47.8 115.585,48.385 115.585,50.685 116.8,51.9 121.4,51.9 123.45,53.95 132.25,53.95 ; U3.3@101.95,58.65 U3.3@102.015,58.65 ; 115.345,48.145 ccw(c114.769,48.721) U2.3@115.516,49.045 ; U2.3@115.66,50.125 cw(c117.193,50.125) 116.109,51.209 ; 121.9,52.4 ccw(c119.813,54.488) v1@122.765,54.499 ; v1(123,54.5) 123.55,53.95 ; v1@123.166,54.666 ccw(c124.895,56.395) C8.2@124.895,53.95 ; 123.258,53.758 ccw(c122.519,54.498) v1@123.565,54.502 ; 127.843,53.95 ccw(c127.843,57.907) C14.1@130.641,55.109 ; 129.774,53.95 ccw(c129.774,55.976) C14.1@131.207,54.543 ; C14.1@130.233,54.854 ccw(c131.303,55.035) 131.303,53.95 ; C14.1@131.022,54.988 ccw(c132.25,55.196) 132.25,53.95 ; JP2.2@135.117,55.657 ccw(c134.434,54.974) 134.434,55.94 ccw(c134.434,56.906) JP2.2@135.117,56.223 ; JP2.2@135.5,55.94 134.24,55.94 ; 132.25,53.95 134.24,55.94 ; 132.25,53.95 134.24,55.94 ; 132.737,54.437 cw(c135.4,51.774) 135.4,55.54 ccw(c135.4,51.774) 132.737,54.437 ; 133.66,55.36 cw(c134.588,54.432) 135.21,55.588 ccw(c134.588,54.432) 133.66,55.36 ; 134.103,55.803 cw(c135.4,54.505) 135.4,56.34 ccw(c135.4,54.505) 134.103,55.803 ; 134.421,56.121 cw(c135.12,55.421) 135.59,56.292 ccw(c135.12,55.421) 134.421,56.121
  Bottom Layer w0.8: v1(123,54.5) 123.2,54.5 123.65,54.95 ; v1@123.027,54.733 ccw(c123.115,55.485) 123.65,54.95 ; v1@123.166,54.334 cw(c124.654,52.846) 124.654,54.95 ; v1(123.4,57.2) 123.4,56.3 124.75,54.95 ; v1@123.634,57.183 ccw(c125.921,57.021) 124.3,55.4 ; C14.1@130.75,55 C14.1@130.8,54.95 123.65,54.95
NetC11_1: C11.1 U1.62 Y1.2 | length 19.1
  Top Layer w0.3: U1.62@116.1,91.3 117,91.3 117.253,91.553 117.253,92.553 118.014,93.314 C11.1@126.35,93.314
  Bottom Layer w0.4: Y1.2@122.7,93.8 123.186,93.328 ; Y1.2@122.7,94.44 122.7,93.814 123.214,93.3 C11.1@126.35,93.3 ; C11.1@125.926,92.876 ccw(c124.901,91.851) 124.901,93.3 ccw(c124.901,94.749) C11.1@125.926,93.724
NetC12_1: C12.1 U1.61 Y1.1 | length 26.5
  Top Layer w0.3: U1.61@116.1,90.8 117.3,90.8 117.717,91.217 117.8,91.3 117.8,91.9 118.4,92.5 125.2,92.5 126.35,91.35 C12.1@126.35,90.2 ; C12.1@126.05,89.95 C12.1@126.3,89.864
  Bottom Layer w0.4: Y1.1@122.559,89.701 cw(c123.762,88.498) 123.762,90.2 ; Y1.1@122.7,89.56 122.7,89.6 123.3,90.2 ; Y1.1@122.841,89.419 cw(c124.728,87.532) 124.728,90.2 ; Y1.1@122.917,90.119 ccw(c123.047,90.453) 123.3,90.2 ; Y1.1@123.124,89.136 cw(c125.694,86.566) C12.1@125.694,90.2 ; Y1.1@123.238,89.825 cw(c123.53,89.97) 123.3,90.2 ; C12.1@125.926,89.776 ccw(c124.901,88.751) 124.901,90.2 ccw(c124.901,91.649) C12.1@125.926,90.624 ; C12.1@126.35,90.2 123.3,90.2
NetC13_1: C13.1 D1.1 JP2.5 JP7.15 JP11.1 R9.1 U1.57 | length 153.2
  Top Layer w0.3: U1.57@116.05,88.8 117.6,88.8 118.1,89.3 ; v1@118.719,89 ccw(c118.1,88.512) 118.1,89.3 ; v1@118.719,89.6 cw(c118.1,90.088) 118.1,89.3 ; v1(119.1,89.3) 118.1,89.3 ; C13.1@119.3,102.8 125.4,102.8 126.7,101.5 128.3,101.5 129.8,103 136.8,103 137.3,102.5 137.3,68.4 136.3,67.4 134.5,67.4 133.9,66.8 133.9,64.2 134.54,63.56 JP2.5@135.5,63.56 ; C13.1@119.789,102.411 cw(c120.728,101.472) 120.728,102.8 cw(c120.728,104.128) C13.1@119.789,103.189 ; R9.1@121.49,102.34 ccw(c120.381,101.231) 120.381,102.8 ccw(c120.381,104.369) R9.1@121.49,103.26 ; R9.1@121.703,102.553 ccw(c121.105,101.955) 121.105,102.8 ccw(c121.105,103.645) R9.1@121.703,103.047 ; R9.1@122.197,102.553 cw(c122.795,101.955) 122.795,102.8 cw(c122.795,103.645) R9.1@122.197,103.047 ; R9.1@122.41,102.34 cw(c123.519,101.231) 123.519,102.8 cw(c123.519,104.369) R9.1@122.41,103.26
  Bottom Layer w0.4: 116.1,102.8 C13.1@119.3,102.8 ; 116.341,108.361 117.73,109.75 JP7.15@117.73,111.4 ; JP7.15@117.306,110.876 cw(c116.281,109.851) 117.73,109.851 cw(c119.179,109.851) JP7.15@118.154,110.876 ; 117.68,109.7 116.1,108.12 116.1,100.3 116.9,99.5 117.9,99.5 D1.1@118.35,99.5 ; D1.1@118.203,99.893 cw(c117.158,99.792) 117.9,99.05 ; 118.287,90.213 cw(c117.373,89.3) v1@118.665,89.3 ; 118.528,89.972 ccw(c119.1,90.544) v1@119.1,89.735 ; D1.1@118.743,99.353 ccw(c118.642,98.308) 117.9,99.05 ; D1.1@118.8,99.95 117.9,99.05 ; C13.1@118.846,102.446 ccw(c117.993,101.593) 117.993,102.8 ccw(c117.993,104.007) C13.1@118.846,103.154 ; v1(119.1,89.3) 119.1,89.4 117.9,90.6 117.9,99.05 ; R9.1@121.4,102.8 121.4,104.5 ; 121.4,103.909 ccw(c122.394,103.909) R9.1@122.024,102.986 ; R9.1@122.173,103.357 cw(c122.631,104.5) 121.4,104.5 ; 122.227,108.1 ccw(c122.227,112.058) JP11.1@125.026,109.259 ; 123.193,108.1 ccw(c123.193,111.092) JP11.1@125.309,108.976 ; 124.158,108.1 ccw(c124.158,110.127) JP11.1@125.591,108.694 ; JP11.1@124.923,108.549 cw(c124.627,108.388) 124.865,108.15 cw(c125.167,107.848) JP11.1@125.284,108.258 ; JP11.1@125.126,108.411 cw(c124.101,107.386) 125.55,107.386 cw(c126.999,107.386) JP11.1@125.974,108.411 ; JP11.1@131.426,108.411 cw(c130.401,107.386) 131.85,107.386 cw(c133.299,107.386) JP11.1@132.274,108.411 ; JP11.1@131.85,108.835 131.85,106.55 130.2,104.9 126.5,104.9 125.55,105.85 JP11.1@125.55,108.835 124.815,108.1 121.2,108.1 120.7,107.6 120.7,105.2 121.4,104.5
NetC15_1: C15.1 U4.1 | length 12.8
  Top Layer w0.3: U4.1@125.5,63.205 125.695,63.205 127.3,61.6 129.11,61.6 C15.1@130.61,63.1 ; U4.1@125.85,63.205 ccw(c126.224,63.205) U4.1@125.96,62.94 ; U4.1@126.15,63.205 ccw(c127.248,63.205) 126.472,62.428 ; U4.1@126.45,63.205 ccw(c128.273,63.205) 126.984,61.916 ; C15.1@129.96,63.1 cw(c128.391,63.1) 129.5,61.99 cw(c130.61,60.88) C15.1@130.61,62.45 ; C15.1@130.26,63.1 cw(c129.415,63.1) 130.013,62.502 cw(c130.61,61.905) C15.1@130.61,62.75
NetC15_2: C15.2 U4.3 | length 8.8
  Top Layer w0.3: U4.3@125.5,65.745 126.955,65.745 128.06,64.64 ; U4.3@126.406,65.639 cw(c126.662,65.383) 126.662,65.745 cw(c126.662,66.107) U4.3@126.406,65.851 ; C15.2@127.607,63.566 ccw(c126.561,64.64) 128.06,64.64 ; C15.2@127.816,63.351 ccw(c127.253,63.929) 128.06,63.929 ccw(c128.867,63.929) C15.2@128.304,63.351 ; C15.2@128.06,63.1 128.06,64.64 ; C15.2@128.513,63.566 cw(c129.559,64.64) 128.06,64.64
NetC16_2: C16.2 U4.2 | length 11.6
  Top Layer w0.3: C16.2@121.798,59.626 ccw(c120.857,60.64) 122.24,60.64 ; C16.2@122.002,59.407 ccw(c121.496,59.952) 122.24,59.952 ccw(c122.984,59.952) C16.2@122.478,59.407 ; C16.2@122.3,59.21 C16.2@122.24,59.15 122.24,60.64 ; C16.2@122.682,59.626 cw(c123.623,60.64) 122.24,60.64 ; U4.2@124.594,64.369 ccw(c124.338,64.113) 124.338,64.475 ccw(c124.338,64.837) U4.2@124.594,64.581 ; U4.2@125.5,64.475 124.2,64.475 123.5,63.775 123.5,61.9 122.24,60.64
NetC17_2: C17.2 U4.6 | length 8.4
  Top Layer w0.3: U4.6@125.5,69.555 127.755,69.555 128.16,69.96 ; U4.6@126.406,69.449 cw(c126.662,69.193) 126.662,69.555 cw(c126.662,69.917) U4.6@126.406,69.661 ; C17.2@127.718,70.974 cw(c126.777,69.96) 128.16,69.96 ; C17.2@127.922,71.193 cw(c127.416,70.648) 128.16,70.648 cw(c128.904,70.648) C17.2@128.398,71.193 ; C17.2@128.16,71.45 128.16,69.96 ; C17.2@128.602,70.974 ccw(c129.543,69.96) 128.16,69.96
NetC18_1: C18.1 U4.5 | length 10.1
  Top Layer w0.3: U4.5@125.5,68.285 129.325,68.285 C18.1@130.71,66.9 ; U4.5@126.406,68.179 cw(c126.662,67.923) 126.662,68.285 cw(c126.662,68.647) U4.5@126.406,68.391 ; C18.1@130.06,66.9 ccw(c128.491,66.9) 129.6,68.009 ccw(c130.71,69.119) C18.1@130.71,67.55 ; C18.1@130.36,66.9 ccw(c129.515,66.9) 130.113,67.497 ccw(c130.71,68.095) C18.1@130.71,67.25
NetC18_2: C18.2 U4.4 | length 6.7
  Top Layer w0.3: U4.4@125.5,67.015 128.045,67.015 C18.2@128.16,66.9 ; U4.4@126.313,67.015 cw(c126.313,65.053) C18.2@127.7,66.44 ; U4.4@126.406,66.909 cw(c126.662,66.653) 126.662,67.015 cw(c126.662,67.377) U4.4@126.406,67.121 ; 126.868,67.015 ccw(c126.868,68.192) C18.2@127.7,67.36 ; 127.037,67.015 cw(c127.037,65.777) C18.2@127.913,66.653
NetJP1_2: JP1.2 R4.2 | length 7.4
  Bottom Layer w0.4: JP1.2@129.071,79.644 ccw(c129.233,80.841) 130.104,80.004 ; JP1.2@129.08,78.94 130.1,80 R4.2@130.1,81.95 ; JP1.2@129.59,79.061 cw(c130.557,79.08) 129.86,79.75 ; R4.2@129.711,81.511 cw(c128.772,80.572) 130.1,80.572 cw(c131.428,80.572) R4.2@130.489,81.511
NetJP3_1: JP3.1 U1.36 | length 105.8
  Top Layer w0.3: U1.36@108.2,83.025 108.2,80.8 101.3,73.9 101.3,65.3 98.9,62.9 97,62.9 96.5,62.4 94.6,62.4 93.8,61.6 93.8,50.1 96.9,47 133.7,47 136.6,49.9 137.2,50.5 137.2,64.4 JP3.1@135.5,66.1 ; JP3.1@135.5,65.5 cw(c135.5,64.051) 136.524,65.076 cw(c137.549,66.1) JP3.1@136.1,66.1
NetJP3_2: JP3.2 U1.40 | length 38
  Top Layer w0.3: U1.40@110.2,82.95 110.2,81.809 110.2,78.5 110.2,76.2 110.9,75.5 111.3,75.1 130.7,75.1 133.7,72.1 133.7,69.3 134.36,68.64 ; JP3.2@134.816,68.355 ccw(c134.36,68.133) 134.36,68.64 ; JP3.2@134.816,68.925 cw(c134.36,69.147) 134.36,68.64 ; JP3.2@135.5,68.64 134.36,68.64
NetJP3_3: JP3.3 U1.44 | length 30.7
  Top Layer w0.3: U1.44@112.2,83 112.2,81.1 113.2,80.1 113.2,78.5 116.1,75.6 131,75.6 134.2,72.4 134.2,71.7 134.72,71.18 JP3.3@135.5,71.18
NetJP3_4: JP3.4 U1.48 | length 32.5
  Top Layer w0.3: U1.48@114.2,82.3 cw(c114.2,81.8) 114.554,82.154 ; U1.48@114.2,82.95 114.2,82.507 115.9,80.807 115.9,79 117.3,77.6 130.1,77.6 131.2,78.7 132.9,78.7 134.2,77.4 134.2,75.02 JP3.4@135.5,73.72 ; 134.22,75 cw(c132.939,73.72) JP3.4@134.75,73.72 ; 134.461,74.759 ccw(c135.4,75.698) JP3.4@135.4,74.37 ; 134.732,74.488 cw(c133.964,73.72) JP3.4@135.05,73.72
NetJP3_5: JP3.5 U1.4 | length 52
  Top Layer w0.3: U1.4@112.7,94.2 112.7,95.993 114.046,97.339 114.046,98.643 114.6,99.196 120.296,99.196 122.2,101.1 125.293,101.1 131.193,95.2 131.7,95.2 133.1,93.8 133.1,92.8 132.4,92.1 130.7,92.1 130.4,91.8 129.7,91.1 129.7,84.2 131.2,82.7 131.2,80.1 131.6,79.7 132,79.3 133.1,79.3 134.8,77.6 135.2,77.2 135.5,76.9 JP3.5@135.5,76.26 ; 135.311,77.089 cw(c134.883,76.662) JP3.5@135.361,76.291
NetJP3_6: JP3.6 U1.8 | length 63.5
  Top Layer w0.3: U1.8@110.7,94.15 110.7,96.4 107.947,99.153 107.854,99.153 107.3,99.707 107.3,100.7 107.8,101.2 108.4,101.8 111,101.8 111.7,101.1 113.7,101.1 115.058,99.742 117.442,99.742 119.3,101.6 125.5,101.6 131.2,95.9 131.8,95.9 133.6,94.1 133.6,92.3 132.8,91.5 131,91.5 130.2,90.7 130.2,84.7 131.8,83.1 131.8,81.2 132.5,80.5 133.8,80.5 JP3.6@135.5,78.8 ; 134.22,80.08 cw(c132.939,78.8) JP3.6@134.75,78.8 ; 134.461,79.839 ccw(c135.4,80.778) JP3.6@135.4,79.45 ; 134.732,79.568 cw(c133.964,78.8) JP3.6@135.05,78.8
NetJP3_7: JP3.7 U1.12 | length 60
  Top Layer w0.3: v1(106.3,97.7) 107,97.7 ; v1@106.429,97.568 cw(c106.781,97.209) 107.136,97.564 ; v1@106.639,97.354 cw(c106.993,96.993) 107.35,97.35 ; v1@106.754,97.53 cw(c107,97.437) 107,97.7 ; v1@106.754,97.87 ccw(c107,97.963) 107,97.7 ; U1.12@108.7,94.15 108.7,96 107,97.7 ; v1@133.4,83.215 cw(c133.4,82.672) 133.784,83.056 ; v1(133.4,83.7) 133.3,83.54 133.42,83.42 JP3.7@135.5,81.34 ; v1@133.585,83.7 ccw(c134.659,83.7) 133.9,82.94 ; v1@133.885,83.7 ccw(c135.684,83.7) 134.412,82.428 ; 134.22,82.62 cw(c132.939,81.34) JP3.7@134.75,81.34 ; 134.461,82.379 ccw(c135.4,83.318) JP3.7@135.4,81.99 ; 134.732,82.108 cw(c133.964,81.34) JP3.7@135.05,81.34
  Bottom Layer w0.4: v1(106.3,97.7) 109.4,97.7 112.4,94.7 112.4,90.2 117.9,84.7 117.9,83.7 119.624,81.976 123.076,81.976 124.367,83.267 132.267,83.267 132.7,83.7 ; v1@106.608,97.392 cw(c107.35,96.65) 107.35,97.7 cw(c107.35,98.75) v1@106.608,98.008 ; 132.35,83.35 cw(c132.744,82.956) v1@133.112,83.374 ; 132.404,83.404 cw(c133.123,82.686) v1@133.391,83.666 ; 132.651,83.651 cw(c133.026,83.276) v1@133.377,83.674 ; v1@133.01,83.507 ccw(c132.7,83.354) 132.7,83.7 ; v1@133.01,83.893 cw(c132.7,84.046) 132.7,83.7 ; v1@133.338,83.555 133.7,83.4 v1(133.4,83.7) 132.7,83.7
NetJP3_8: JP3.8 U1.16 | length 55.7
  Top Layer w0.3: v1@105.5,94.4 105.1,94.6 v1(105.4,94.3) 105.55,94.15 U1.16@106.7,94.15 cw(c106.7,95.012) v1@105.932,94.62 ; v1@105.665,94.484 ccw(c106.21,94.762) 106.21,94.15 ; 132.401,82.599 cw(c131.403,81.6) v1@132.815,81.6 ; 132.643,82.357 ccw(c133.3,83.014) v1@133.3,82.085 ; v1(133.3,81.6) 133.3,81.8 132.3,82.8 132.3,84.2 132.9,84.8 133.8,84.8 134.72,83.88 JP3.8@135.5,83.88 ; 134.14,84.46 ccw(c134.609,84.929) JP3.8@135.009,84.399 ; 134.384,84.216 ccw(c134.819,84.651) JP3.8@135.189,84.16
  Bottom Layer w0.4: v1@105.5,93.965 cw(c105.5,92.915) 106.243,93.657 cw(c106.985,94.4) v1@105.935,94.4 ; v1@105.5,94.4 118.6,81.3 123.8,81.3 124.4,80.7 127.2,80.7 127.7,80.2 127.7,78.1 128.2,77.6 130.3,77.6 132.2,79.5 v1(133.3,81.6) ; v1@132.885,81.47 cw(c131.882,81.157) 132.813,80.67 cw(c133.743,80.182) v1@133.43,81.185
